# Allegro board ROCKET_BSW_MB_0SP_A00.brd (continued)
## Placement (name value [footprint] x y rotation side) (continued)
PC4708  SC22U6D3V3MX-1-GP  [C603H40]  58.14 62.77 180 top
PC4710  SC330P50V3KX-GP  [C603]  45.5 55.3 90 bottom
PC4801  SC10U25V5KX-GP  [C805H56]  37.5 71.31 0 bottom
PC4802  SC560P50V2KX-2GP  [C402H24]  31.01 83.69 270 top
PC4803  SCD1U16V2KX-3GP  [C402H22]  29.92 73.55 270 top
PC4804  SC470P50V2KX-3GP  [C402H22]  25.96 78.84 0 top
PC4805  SC470P50V2KX-3GP  [C402H22]  29.72 83.14 180 top
PC4806  SCD01U50V2KX-1GP  [C402H22]  34.87 75.05 180 top
PC4807  SC1U10V2KX-1GP  [C402H22]  28.67 74.89 90 top
PC4808  SC2D2U10V3KX-1GP  [C603H36]  33.77 80.68 0 bottom
PC4809  SCD1U16V2KX-3GP  [C402H22]  34.53 73.78 90 top
PC4810  SC100P50V2JN-3GP  [C402H22]  31.01 82.88 270 top
PC4811  SC10U25V5KX-GP  [C805H56]  35.67 71.31 0 bottom
PC4812  SC1KP50V2KX-1GP  [C402H22]  32.71 82.87 90 top
PC4813  SCD22U25V3KX-GP  [C603H40]  34.03 74.82 180 bottom
PC4814  SCD1U16V2KX-3GP  [C402H22]  35.54 79.52 270 top
PC4815  SC1KP50V2KX-1GP  [C402H22]  27.84 73.39 180 top
PC4816  SCD015U25V2KX-GP  [C402H22]  26.77 81.38 180 top
PC4817  SC330P50V3KX-GP  [C603]  45.13 76.27 90 bottom
PC4818  SC100P50V2JN-3GP  [C402H22]  26.34 80.11 270 top
PC4819  SC2200P50V2KX-2GP  [C402H22]  26.22 73.38 0 top
PC4820  SC22U6D3V3MX-1-GP  [C603H40]  55.88 72.61 180 top
PC4821  SC22U6D3V3MX-1-GP  [C603H40]  57.15 72.61 180 top
PC4822  SC22U6D3V3MX-1-GP  [C603H40]  54.61 72.61 180 top
PC4823  SCD1U16V2KX-3GP  [C402H22]  34.1 67.26 90 bottom
PC4834  SCD1U16V2KX-3GP  [C402H22]  28.93 71.92 90 top
PC4839  SCD1U16V2KX-3GP  [C402H22]  27.2 71.92 270 top
PC5000  SC1U10V2KX-1GP  [C402H22]  37.02 47.64 180 bottom
PC5001  SCD1U16V2KX-3GP  [C402H22]  90.14 88.05 0 top
PC5002  SC330P50V2KX-3GP  [C402H22]  92.42 87.92 270 top
PC5003  SCD1U16V2KX-3GP  [C402H22]  83.35 82.82 90 bottom
PC5004  SC4D7U25V5KX-GP  [C805H54]  84.99 90.25 270 bottom
PC5005  SC22U6D3V5MX-2GP  [C805H58]  82.9 79.66 90 bottom
PC5007  SC1U10V2KX-1GP  [C402H22]  93.03 84.29 90 top
PC5008  SC4D7U25V5KX-GP  [C805H54]  84.99 92.05 270 bottom
PC5009  SC2D2U10V3KX-1GP  [C603H36]  91.55 82.66 180 bottom
PC5010  SC22U6D3V5MX-2GP  [C805H58]  82.9 81.46 90 bottom
PC5011  SC22U6D3V5MX-2GP  [C805H58]  81.76 74.25 90 bottom
PC5012  SC22U6D3V5MX-2GP  [C805H58]  81.76 77.85 90 bottom
PC5013  SC22U6D3V5MX-2GP  [C805H58]  81.76 76.05 90 bottom
PC5014  SC10U6D3V3MX-GP  [C603H38]  32.08 50.51 0 bottom
PC5015  SC1U10V2KX-1GP  [C402H22]  33.12 50.49 0 bottom
PC5016  SC10U6D3V3MX-GP  [C603H38]  30.81 50.51 0 bottom
PC5017  SC22P50V2JN-4GP  [C402H22]  34.56 47.64 0 bottom
PC5018  SC22U6D3V3MX-1-GP  [C603H40]  42.53 50.68 0 bottom
PC5019  SC22U6D3V3MX-1-GP  [C603H40]  43.82 50.68 0 bottom
PC5101  SC22U6D3V5MX-2GP  [C805H58]  89.95 27.44 0 bottom
PC5102  SCD1U16V2KX-3GP  [C402H22]  89.54 22.41 180 bottom
PC5103  SC22U6D3V5MX-2GP  [C805H58]  92.66 22.41 180 bottom
PC5104  SC22U6D3V5MX-2GP  [C805H58]  91.76 27.44 0 bottom
PC5105  SC22U6D3V5MX-2GP  [C805H58]  90.86 22.41 180 bottom
PC5106  SC10U25V5KX-GP  [C805H56]  74.75 20.57 90 bottom
PC5107  SCD01U50V2KX-1GP  [C402H22]  74.64 23.68 90 bottom
PC5108  SC10U25V5KX-GP  [C805H56]  74.75 22.37 90 bottom
PC5110  SC1U10V2KX-1GP  [C402H22]  78.28 29.16 0 bottom
PC5111  SC1U10V2KX-1GP  [C402H22]  97.65 23.84 0 bottom
PC5112  SC330P50V2KX-3GP  [C402H22]  75.12 28.23 270 top
PC5113  SC2D2U10V3KX-1GP  [C603H36]  80.24 29.6 0 bottom
PC5114  SC22U6D3V5MX-2GP  [C805H58]  105.82 20.32 180 bottom
PC5115  SC10U6D3V3MX-GP  [C603H38]  102.54 25.71 90 bottom
PC5116  SCD1U16V2KX-3GP  [C402H22]  98.92 19.94 270 top
PC5117  SCD1U25V2KX-GP  [C402H22]  84.38 23.4 90 top
PC5118  SCD1U16V2KX-3GP  [C402H22]  102.59 24.64 90 bottom
PC5119  SCD1U16V2KX-3GP  [C402H22]  95.86 22.16 90 bottom
PC5120  SCD1U16V2KX-3GP  [C402H22]  97.36 21.01 180 bottom
PC5138  SCD1U16V2KX-3GP  [C402H22]  75.12 25.85 180 bottom
PC5219  SC10U6D3V3MX-GP  [C603H38]  30.7 44.6 0 bottom
PC5220  SC10U6D3V3MX-GP  [C603H38]  31.97 44.6 0 bottom
PC5221  SC1U10V2KX-1GP  [C402H22]  33.04 44.6 0 bottom
PC5222  SC22P50V2JN-4GP  [C402H22]  34.7 39.77 90 bottom
PC5223  SC22U6D3V3MX-1-GP  [C603H40]  43.04 42.18 270 bottom
PC5224  SC22U6D3V3MX-1-GP  [C603H40]  43.04 43.45 270 bottom
PC5225  SC1U10V2KX-1GP  [C402H22]  36.73 41.38 180 bottom
PC5301  SC1U10V2KX-1GP  [C402H22]  118.98 100.56 270 top
PC5306  SC1U10V2KX-1GP  [C402H22]  116.88 100.2 90 top
PC5326  SCD1U16V2KX-3GP  [C402H22]  120.88 99.39 0 bottom
PC5401  SC1U10V2KX-1GP  [C402H22]  49 36.94 270 bottom
PC5402  SC10U6D3V3MX-GP  [C603H38]  51.89 40.93 270 bottom
PC5404  SC10U25V5KX-GP  [C805H56]  47.02 47.22 0 bottom
PC5405  SC33P50V2JN-3GP  [C402H22]  45.28 46.59 90 bottom
PC5407  SC10U25V5KX-GP  [C805H56]  48.82 47.22 0 bottom
PC5427  SCD1U16V2KX-3GP  [C402H22]  43.22 39.01 0 bottom
PD4301  P6SMB27A-GP  [DO214AAAKH97]  21.79 71.61 270 bottom
PD4302  SMF18AT1G-GP  [SOD123FLAKH40]  113.28 20.25 270 bottom
PD4303  LBAV99LT1G-1-GP  [SOT23-2D4-312H44]  23.73 63.35 270 bottom
PD4401  SD103AWS-2-GP  [SOD323AKH38]  136.17 15.78 180 top
PD4404  1N4148WS-7-F-GP  [SOD323AKH42]  135.25 36.42 0 bottom
PG4402  GAP-CLOSE-PWR-3-GP  [GAP-CLOSE-PWR-3]  145.71 21.92 0 bottom
PG4403  GAP-CLOSE-PWR-3-GP  [GAP-CLOSE-PWR-3]  145.73 23.65 0 bottom
PG4404  GAP-CLOSE-PWR-3-GP  [GAP-CLOSE-PWR-3]  123.49 24.84 270 bottom
PG4405  GAP-CLOSE-PWR-3-GP  [GAP-CLOSE-PWR-3]  121.77 24.84 270 bottom
PG4407  GAP-CLOSE-PWR-3-GP  [GAP-CLOSE-PWR-3]  132.89 8.59 270 top
PG4408  GAP-CLOSE-PWR-3-GP  [GAP-CLOSE-PWR-3]  131.98 8.59 270 top
PG4409  GAP-CLOSE-PWR-3-GP  [GAP-CLOSE-PWR-3]  123.49 20.32 90 bottom
PG4410  GAP-CLOSE-PWR-3-GP  [GAP-CLOSE-PWR-3]  121.76 20.33 90 bottom
PG4411  GAP-CLOSE-PWR-3-GP  [GAP-CLOSE-PWR-3]  133.77 13.11 90 bottom
PG4517  GAP-CLOSE-PWR-3-GP  [GAP-CLOSE-PWR-3]  23.55 29.67 180 bottom
PG4519  GAP-CLOSE-PWR-3-GP  [GAP-CLOSE-PWR-3]  21.17 19.71 0 bottom
PG4521  GAP-CLOSE-PWR-3-GP  [GAP-CLOSE-PWR-3]  23.63 17.26 270 bottom
PG4523  GAP-CLOSE-PWR-3-GP  [GAP-CLOSE-PWR-3]  21.17 20.47 0 bottom
PG4525  GAP-CLOSE-PWR-3-GP  [GAP-CLOSE-PWR-3]  42.36 16.27 90 bottom
PG4527  GAP-CLOSE-PWR-3-GP  [GAP-CLOSE-PWR-3]  23.55 31.95 180 bottom
PG4528  GAP-CLOSE-PWR-3-GP  [GAP-CLOSE-PWR-3]  23.55 28.91 180 bottom
PG4529  GAP-CLOSE-PWR-3-GP  [GAP-CLOSE-PWR-3]  23.55 28.14 180 bottom
PG4532  GAP-CLOSE-PWR-3-GP  [GAP-CLOSE-PWR-3]  21.17 24.28 0 bottom
PG4533  GAP-CLOSE-PWR-3-GP  [GAP-CLOSE-PWR-3]  21.17 21.99 0 bottom
PG4534  GAP-CLOSE-PWR-3-GP  [GAP-CLOSE-PWR-3]  45.57 19.8 180 top
PG4535  GAP-CLOSE-PWR-3-GP  [GAP-CLOSE-PWR-3]  24.18 26.95 270 bottom
PG4537  GAP-CLOSE-PWR-3-GP  [GAP-CLOSE-PWR-3]  21.17 21.23 0 bottom
PG4538  GAP-CLOSE-PWR-3-GP  [GAP-CLOSE-PWR-3]  21.17 17.42 0 bottom
PG4539  GAP-CLOSE-PWR-3-GP  [GAP-CLOSE-PWR-3]  23.55 30.43 180 bottom
PG4540  GAP-CLOSE-PWR-3-GP  [GAP-CLOSE-PWR-3]  21.17 18.18 0 bottom
PG4541  GAP-CLOSE-PWR-3-GP  [GAP-CLOSE-PWR-3]  21.17 18.94 0 bottom
PG4542  GAP-CLOSE-PWR-3-GP  [GAP-CLOSE-PWR-3]  37.45 27.22 90 top
PG4544  GAP-CLOSE-PWR-3-GP  [GAP-CLOSE-PWR-3]  21.17 23.52 0 bottom
PG4545  GAP-CLOSE-PWR-3-GP  [GAP-CLOSE-PWR-3]  21.17 22.75 0 bottom
PG4546  GAP-CLOSE-PWR-3-GP  [GAP-CLOSE-PWR-3]  23.55 31.19 180 bottom
PG4707  GAP-CLOSE-PWR-3-GP  [GAP-CLOSE-PWR-3]  48.59 61.52 180 bottom
PG4709  GAP-CLOSE-PWR-3-GP  [GAP-CLOSE-PWR-3]  51.92 61.52 0 bottom
PG4801  GAP-CLOSE-PWR-3-GP  [GAP-CLOSE-PWR-3]  51.79 71.5 0 bottom
PG4802  GAP-CLOSE-PWR-3-GP  [GAP-CLOSE-PWR-3]  49.63 71.5 180 bottom
PG5001  GAP-CLOSE-PWR-3-GP  [GAP-CLOSE-PWR-3]  84.23 68.97 90 bottom
PG5002  GAP-CLOSE-PWR-3-GP  [GAP-CLOSE-PWR-3]  44.53 48.26 0 bottom
PG5003  GAP-CLOSE-PWR-3-GP  [GAP-CLOSE-PWR-3]  44.53 49.02 0 bottom
PG5004  GAP-CLOSE-PWR-3-GP  [GAP-CLOSE-PWR-3]  30.78 48.57 90 bottom
PG5005  GAP-CLOSE-PWR-3-GP  [GAP-CLOSE-PWR-3]  31.54 48.57 90 bottom
PG5101  GAP-CLOSE-PWR-3-GP  [GAP-CLOSE-PWR-3]  79.22 20.61 180 bottom
PG5102  GAP-CLOSE-PWR-3-GP  [GAP-CLOSE-PWR-3]  93.83 25.07 0 bottom
PG5103  GAP-CLOSE-PWR-3-GP  [GAP-CLOSE-PWR-3]  79.22 21.38 180 bottom
PG5104  GAP-CLOSE-PWR-3-GP  [GAP-CLOSE-PWR-3]  93.83 26.6 0 bottom
PG5105  GAP-CLOSE-PWR-3-GP  [GAP-CLOSE-PWR-3]  93.83 25.83 0 bottom
PG5106  GAP-CLOSE-PWR-3-GP  [GAP-CLOSE-PWR-3]  79.22 22.14 180 bottom
PG5107  GAP-CLOSE-PWR-3-GP  [GAP-CLOSE-PWR-3]  79.22 19.85 180 bottom
PG5108  GAP-CLOSE-PWR-3-GP  [GAP-CLOSE-PWR-3]  93.83 24.31 0 bottom
PG5109  GAP-CLOSE-PWR-3-GP  [GAP-CLOSE-PWR-3]  93.83 27.36 0 bottom
PG5117  GAP-CLOSE-PWR-3-GP  [GAP-CLOSE-PWR-3]  105.92 22.72 90 bottom
PG5118  GAP-CLOSE-PWR-3-GP  [GAP-CLOSE-PWR-3]  106.68 22.72 90 bottom
PG5207  GAP-CLOSE-PWR-3-GP  [GAP-CLOSE-PWR-3]  31.79 42.61 90 bottom
PG5208  GAP-CLOSE-PWR-3-GP  [GAP-CLOSE-PWR-3]  31.02 42.61 90 bottom
PG5209  GAP-CLOSE-PWR-3-GP  [GAP-CLOSE-PWR-3]  42.67 44.97 0 bottom
PG5210  GAP-CLOSE-PWR-3-GP  [GAP-CLOSE-PWR-3]  42.67 45.73 0 bottom
PG5408  GAP-CLOSE-PWR-3-GP  [GAP-CLOSE-PWR-3]  50.44 45.73 0 bottom
PG5409  GAP-CLOSE-PWR-3-GP  [GAP-CLOSE-PWR-3]  50.44 46.65 0 bottom
PL4401  IND-2D2UH-179-GP  [L7066-1830-UH119]  129.28 21.58 90 bottom
PL4501  COIL-1D5UH-43-GP  [L4947-1015H119]  33.14 29.3 90 bottom
PL4502  COIL-1D5UH-43-GP  [L4947-1015H119]  34.13 21.22 90 bottom
PL4701  IND-D36UH-26-GP-U  [L6965-1330-UH119]  50.21 61.52 270 bottom
PL4801  IND-D22UH-37-GP  [L7066-1830-UH119]  50.67 71.5 270 bottom
PL5001  COIL-1UH-73-GP  [L4947-1115H119]  87.68 80.09 180 bottom
PL5002  IND-2D2UH-296-GP  [L3030-3009H60]  39.67 49.94 270 bottom
PL5101  COIL-1UH-73-GP  [L4947-1115H119]  84.93 24.86 270 bottom
PL5201  IND-2D2UH-296-GP  [L3030-3009H60]  39.59 44.42 270 bottom
PQ4301  DMN5L06K-7-GP  [SOT23DGS2D4H48]  27.58 64.36 180 bottom
PQ4302  LMBT3904LT1G-GP  [SOT23CBE2D4H44]  31.36 66.89 270 bottom
PQ4304  LTC024EUB-FS8-GP  [SC70-2D2-312H44]  19.36 67.3 180 bottom
PQ4305  LTA024EUB-FS8-GP  [SC70-2D2-312H44]  22.38 67.3 0 bottom
PQ4309  2N7002K-2-GP  [SOT23DGS2D4H44]  30.02 70.69 180 bottom
PQ4402  2N7002KDW-GP  [SOT-363H44]  148.97 26.31 270 bottom
PQ4407  2N7002KDW-GP  [SOT-363H44]  135.7 9.65 180 bottom
PQ4408  2N7002KDW-GP  [SOT-363H44]  149.11 21.53 270 bottom
PQ4409  LMBT3906LT1G-1-GP  [SOT23CBE2D4H44]  138.07 35.17 0 bottom
PQ4410  2N7002KDW-GP  [SOT-363H44]  135.56 30.84 270 bottom
PQ4414  2N7002K-2-GP  [SOT23DGS2D4H44]  142.81 32.24 270 bottom
PR4168  4K02R2F-GP  [R402H16]  25.51 52.52 180 bottom
PR4302  15KR2F-GP  [R402H16]  27.9 68.18 180 top
PR4303  10KR2J-3-GP  [R402H16]  29.85 64.85 0 top
PR4306  2K2R2J-2-GP  [R402H16]  20.88 62.87 180 top
PR4307  33R2J-2-GP  [R402H16]  17.68 63.73 180 bottom
PR4309  240KR3-GP  [R603H22]  26.33 67.92 180 bottom
PR4310  47KR3J-L-GP  [R603H22]  27.6 67.92 0 bottom
PR4311  100KR2J-1-GP  [R402H16]  27.48 66.92 90 top
PR4312  1KR2J-1-GP  [R402H16]  28.53 66.02 270 top
PR4316  3K3R6J-GP  [R1206H28]  28.99 73.63 270 bottom
PR4401  10KR2F-2-GP  [R402H16]  144.86 21.78 0 top
PR4402  D01R3721F-GP-U  [R3720H40]  143.51 22.78 0 bottom
PR4403  100KR2J-1-GP  [R402H16]  143.73 20.46 270 bottom
PR4404  3KR5J-GP  [R805H24]  146.25 14.68 0 bottom
PR4405  470KR2J-2-GP  [R402H16]  119.34 23.7 0 top
PR4406  0R2J-2-GP  [R402H16]  126.8 14.58 0 top
PR4407  287KR2F-GP  [R402H16]  127.22 10.31 90 top
PR4408  10R5J-GP  [R805H24]  130.32 17.49 0 top
PR4409  -  [0R0603-PAD]  133.32 16.46 0 bottom
PR4410  6D8R2F-GP  [R402H16]  142.39 29.1 0 bottom
PR4411  102KR2F-GP  [R402H16]  127.27 11.41 90 top
PR4412  3K3R2F-2-GP  [R402H16]  132.03 7.3 0 bottom
PR4413  169KR2F-L-GP  [R402H16]  130.45 12.2 270 bottom
PR4414  3D3MR2J-GP  [R402H16]  128.24 12.68 0 top
PR4415  3K3R2F-2-GP  [R402H16]  131.18 7.3 0 bottom
PR4416  D01R3721F-GP-U  [R3720H40]  122.64 22.62 90 bottom
PR4417  100KR2J-1-GP  [R402H16]  134.55 8.86 270 top
PR4418  0R2J-2-GP  [R402H16]  136.04 11.31 270 top
PR4419  100KR2J-1-GP  [R402H16]  149.48 19.15 0 bottom
PR4420  7D5R2F-GP  [R402H16]  136.22 12.39 90 top
PR4421  10R2F-L-GP  [R402H14]  136.08 13.3 90 top
PR4422  -  [0R0402-PAD]  126.02 9.37 270 top
PR4423  59KR2F-GP  [R402H16]  133.57 10.7 0 bottom
PR4424  8K45R2F-2-GP  [R402H16]  132.68 10.32 0 bottom
PR4425  100KR2J-1-GP  [R402H16]  126.91 12.62 270 bottom
PR4426  -  [0R0402-PAD]  149.28 23.61 270 bottom
PR4427  78K7R2F-GP  [R402H16]  135.76 6.91 180 bottom
PR4428  100KR2J-1-GP  [R402H16]  148.1 18.74 270 bottom
PR4429  309KR2F-GP  [R402H16]  134.92 6.91 0 bottom
PR4430  100KR2J-1-GP  [R402H16]  127.12 12.87 0 top
PR4431  47KR2F-GP  [R402H16]  130.45 11.38 270 bottom
PR4432  120KR2F-L-GP  [R402H16]  125.24 13.27 270 top
PR4433  120KR2F-L-GP  [R402H16]  124.93 10.74 270 top
PR4434  100KR2J-1-GP  [R402H16]  124.93 11.57 90 top
PR4435  10KR2F-2-GP  [R402H16]  136.06 10.47 90 top
PR4436  120KR2F-L-GP  [R402H16]  148.1 19.57 90 bottom
PR4437  160KR2F-GP  [R402H16]  149.25 14.36 90 top
PR4438  100KR2J-1-GP  [R402H16]  125.23 12.43 270 top
PR4446  20KR2F-L-GP  [R402H16]  145.81 30.08 90 bottom
PR4448  0R2J-2-GP  [R402H16]  140.29 28.69 270 bottom
PR4454  10R2F-L-GP  [R402H14]  140.3 29.52 270 bottom
PR4464  680KR2J-GP  [R402H16]  139.33 32.44 180 bottom
PR4465  0R2J-2-GP  [R402H16]  141.57 34.44 90 bottom
PR4466  0R2J-2-GP  [R402H16]  139.05 30.35 270 bottom
PR4467  1MR2J-1-GP  [R402H16]  137.94 37.48 90 bottom
PR4468  0R2J-2-GP  [R402H16]  140.13 38.55 90 bottom
PR4469  100KR2J-1-GP  [R402H16]  140.29 36.21 0 bottom
PR4470  100KR2F-L1-GP  [R402H16]  132.9 29.6 90 bottom
PR4472  100KR2F-L1-GP  [R402H16]  146.81 34.53 270 bottom
PR4473  10KR2F-2-GP  [R402H16]  134.83 32.79 270 bottom
PR4474  100KR2J-1-GP  [R402H16]  143.28 34.44 90 bottom
PR4475  0R2J-2-GP  [R402H16]  138.5 32.44 180 bottom
PR4476  0R2J-2-GP  [R402H16]  139 31.17 90 bottom
PR4501  -  [0R0603-PAD]  38.24 33.27 270 top
PR4502  -  [0R0603-PAD]  39.93 23.62 270 top
PR4504  -  [0R0402-PAD]  47.38 29.3 0 bottom
PR4506  1KR2F-3-GP  [R402H16]  39.95 26.79 180 bottom
PR4507  1KR2F-3-GP  [R402H16]  41.44 16.4 0 top
PR4510  -  [0R0402-PAD]  48.22 21.43 180 top
PR4511  -  [0R0402-PAD]  48.29 18.35 90 top
PR4512  1KR2F-3-GP  [R402H16]  46.51 19.27 270 bottom
PR4513  200KR2F-L1-GP  [R402H16]  48.2 19.27 270 bottom
PR4514  -  [0R0402-PAD]  47.79 19.16 270 top
PR4515  1KR2F-3-GP  [R402H16]  46.56 28.13 180 bottom
PR4516  1MR2J-1-GP  [R402H16]  47.85 17 0 top
PR4517  200KR2F-L1-GP  [R402H16]  44.78 28.13 0 bottom
PR4518  1MR2J-1-GP  [R402H16]  41.92 28.59 90 top
PR4532  -  [0R0603-PAD]  38.06 25.85 90 top
PR4534  100KR2J-1-GP  [R402H16]  45.67 29.82 180 bottom
PR4601  200R2F-L-GP  [R402H16]  32.45 63.54 270 top
PR4602  200R2F-L-GP  [R402H16]  32.69 67.03 90 top
PR4603  47R2F-GP  [R402H16]  23.36 56.12 90 top
PR4604  1KR2F-3-GP  [R402H16]  24.44 57.01 0 bottom
PR4605  -  [0R0402-PAD]  22.27 60.25 270 top
PR4606  75KR2F-GP  [R402H16]  25.17 50.83 0 bottom
PR4607  1KR2J-1-GP  [R402H16]  33.55 60.89 180 bottom
PR4609  560KR2F-GP  [R402H16]  21.62 52.46 270 top
PR4610  1K5R2F-2-GP  [R402H16]  22.27 58.62 270 top
PR4612  2D2R3-1-U-GP  [R603H22]  33.17 59.42 270 bottom
PR4613  10R2J-2-GP  [R402H14]  28.55 51.53 90 bottom
PR4614  100KR2F-L1-GP  [R402H16]  25.99 50.83 0 bottom
PR4615  14K7R2F-L-GP  [R402H16]  24.48 53.61 180 bottom
PR4616  1K3R2F-1-GP  [R402H16]  22.99 53.62 270 top
PR4617  215KR3F-1-GP  [R603H22]  27.04 50.82 180 bottom
PR4619  46K4R2F-2-GP  [R402H16]  21.72 51.19 0 top
PR4620  2D2R3J-2-GP  [R603H22]  23.44 59.67 270 bottom
PR4621  56D2R2F  [R402H16]  27.04 61.64 180 bottom
PR4635  20KR2J-L2-GP  [R402H16]  26.2 61.38 180 bottom
PR4637  1R3J-L1-GP  [R603H22]  33.68 53.26 90 bottom
PR4638  10KR2J-3-GP  [R402H16]  22.52 61.09 270 top
PR4640  -  [0R0402-PAD]  27.88 61.62 0 bottom
PR4643  10KR2F-2-GP  [R402H16]  34.07 55.65 0 bottom
PR4644  -  [0R0402-PAD]  32.23 54.32 270 bottom
PR4645  200R2J-L1-GP  [R402H16]  32.04 62.64 180 bottom
PR4648  NTC-100K-20-GP  [NTC-402H24-U]  49.5 57.19 270 bottom
PR4649  10KR2J-3-GP  [R402H16]  33.63 61.32 0 top
PR4652  -  [0R0402-PAD]  58.82 43.59 315 top
PR4658  -  [0R0402-PAD]  59.42 43 315 top
PR4660  -  [0R0402-PAD]  32.8 55.16 270 bottom
PR4661  NTC-100K-20-GP  [NTC-402H24-U]  45.41 56.5 90 bottom
PR4663  49D9R2F-GP  [R402H16]  29.56 61.62 0 bottom
PR4665  300R2F-GP  [R402H16]  31.55 67.87 270 top
PR4669  20R2J-3-GP  [R402H16]  28.72 61.62 0 bottom
PR4676  100R2F-L1-GP-U  [R402H14]  62.72 43.72 270 top
PR4678  100R2F-L1-GP-U  [R402H14]  62.72 44.55 270 top
PR4684  31K6R2F-GP  [R402H16]  29.19 53.24 270 bottom
PR4704  2D2R5F-2-GP  [R805H24]  47.59 56.32 180 bottom
PR4801  47R2F-GP  [R402H16]  26.34 77.59 90 top
PR4802  560KR2F-GP  [R402H16]  28.77 78.82 270 bottom
PR4803  1KR2F-3-GP  [R402H16]  26.77 78.84 0 top
PR4804  200R2F-L-GP  [R402H16]  34.35 69.53 180 bottom
PR4805  200R2F-L-GP  [R402H16]  33.52 69.53 180 bottom
PR4807  -  [0R0402-PAD]  30.82 69.15 0 top
PR4808  -  [0R0402-PAD]  27.53 70.67 180 top
PR4809  -  [0R0402-PAD]  28.39 70.66 180 top
PR4810  NTC-100K-20-GP  [NTC-402H24-U]  50.32 67.13 270 bottom
PR4812  NTC-100K-20-GP  [NTC-402H24-U]  40.41 76.51 270 bottom
PR4813  10KR2J-3-GP  [R402H16]  29.92 72.74 270 top
PR4814  20KR2J-L2-GP  [R402H16]  31.14 70.4 270 top
PR4816  56D2R2F  [R402H16]  30.93 71.93 270 top
PR4817  2D2R3J-2-GP  [R603H22]  29.71 75.35 90 bottom
PR4818  1R3J-L1-GP  [R603H22]  32.87 78.3 0 bottom
PR4819  34KR2F-GP  [R402H16]  28.88 83.14 180 top
PR4820  3K6R2F-GP  [R402H16]  28.07 83.14 180 top
PR4821  41K2R2F-GP  [R402H16]  34.12 82.24 180 top
PR4822  48D7KR2F-GP  [R402H16]  35.54 80.37 90 top
PR4823  2D2R3-1-U-GP  [R603H22]  32.76 74.82 180 bottom
PR4824  10R2J-2-GP  [R402H14]  32.72 83.69 270 top
PR4825  75KR2F-GP  [R402H16]  30.58 84.95 0 top
PR4827  1KR2J-1-GP  [R402H16]  35.71 75.05 180 top
PR4828  14K7R2F-L-GP  [R402H16]  27.23 83.14 180 top
PR4830  100KR2F-L1-GP  [R402H16]  31.42 84.95 0 top
PR4831  1K3R2F-1-GP  [R402H16]  25.93 81.39 0 top
PR4832  200KR3F-GP  [R603H22]  33.06 84.75 90 top
PR4833  10KR2F-2-GP  [R402H16]  36.83 79.11 180 top
PR4834  -  [0R0402-PAD]  35.54 78.71 90 top
PR4835  1K5R2F-2-GP  [R402H16]  27.03 73.39 0 top
PR4836  -  [0R0402-PAD]  28.66 73.39 0 top
PR4843  300R2F-GP  [R402H16]  32.68 69.53 180 bottom
PR4847  2D2R5F-2-GP  [R805H24]  47.77 76.27 90 bottom
PR4854  49D9R2F-GP  [R402H16]  33.3 71.78 0 top
PR4855  20R2J-3-GP  [R402H16]  32.43 71.78 0 top
PR4875  200R2J-L1-GP  [R402H16]  34.13 71.78 0 top
PR5001  -  [0R0603-PAD]  86.92 86.58 0 top
PR5002  470KR2F-GP  [R402H16]  92.3 87 270 bottom
PR5003  1MR2J-1-GP  [R402H16]  89.31 88.05 0 top
PR5004  -  [0R0402-PAD]  90.4 90.96 0 top
PR5005  100KR2F-L1-GP  [R402H16]  92.89 85.14 90 top
PR5006  100R2F-L1-GP-U  [R402H14]  93.7 87.5 0 top
PR5007  -  [0R0402-PAD]  91.34 84.28 270 top
PR5008  1KR2J-1-GP  [R402H16]  92.3 87.82 90 bottom
PR5009  -  [0R0402-PAD]  35.37 47.66 180 top
PR5010  53K6R2F-GP  [R402H16]  35.38 47.64 180 bottom
PR5011  49K9R2F-L-GP  [R402H16]  33.75 47.64 0 bottom
PR5012  10KR2J-3-GP  [R402H16]  32.96 47.51 90 top
PR5013  100KR2J-1-GP  [R402H16]  88.97 91.21 0 top
PR5014  75KR2F-GP  [R402H16]  92.42 87.11 270 top
PR5039  10R2F-L-GP  [R402H14]  93.42 85.98 90 top
PR5066  -  [0R0402-PAD]  88.51 89.94 90 top
PR5101  -  [0R0603-PAD]  82.21 23.52 90 top
PR5102  -  [0R0402-PAD]  79.1 29.16 0 bottom
PR5103  42K2R2F-L-GP  [R402H16]  75.12 29.05 270 top
PR5104  33K2R2F-GP  [R402H16]  73.75 28.62 180 top
PR5105  -  [0R0402-PAD]  74.18 27.38 90 top
PR5106  0R2J-2-GP  [R402H16]  73.79 29.1 180 bottom
PR5107  -  [0R0402-PAD]  75.11 25.6 90 top
PR5114  -  [0R0402-PAD]  95.84 22 90 top
PR5117  -  [0R0402-PAD]  97.34 21.71 0 top
PR5125  -  [0R0402-PAD]  95.53 20.59 90 top
PR5201  -  [0R0402-PAD]  37.6 41.38 0 bottom
PR5202  20KR2J-L2-GP  [R402H16]  38.45 41.37 0 bottom
PR5211  100KR2F-L1-GP  [R402H16]  34.7 41.17 270 bottom
PR5213  49K9R2F-L-GP  [R402H16]  34.7 42.01 90 bottom
PR5218  10KR2J-3-GP  [R402H16]  32.81 41.37 270 bottom
PR5315  0R2J-2-GP  [R402H16]  121.7 99.39 180 bottom
PR5401  47KR2J-2-GP  [R402H16]  44.04 39.01 0 bottom
PR5417  -  [0R0402-PAD]  42.39 39.02 180 bottom
PR5419  7K32R2F-GP  [R402H16]  45.28 45.77 90 bottom
PR5420  13K3R2F-L1-GP  [R402H16]  45.28 47.4 270 bottom
PT4701  ST330U2D5VBM-4-GP  [CT3528H79]  56.49 64.26 0 bottom
PT4702  SE33U25VM-11-GP  [CT7343H83]  39.62 55.69 270 bottom
PT4801  ST330U2D5VBM-4-GP  [CT3528H79]  57.09 73.82 0 bottom
PU4301  SI7121DN-T1-GE3-GP  [PPAK-8P-2H45]  143.13 12.51 90 bottom
PU4402  SI7121DN-T1-GE3-GP  [PPAK-8P-2H45]  143.12 16.62 0 bottom
PU4403  SI7121DN-T1-GE3-GP  [PPAK-8P-2H45]  118.5 21.54 0 bottom
PU4404  BQ24727RGRR-1-GP  [QFN20G3D5-G2D15H40]  132.27 12.13 90 top
PU4405  HS8K11TB-GP  [DFN8F3-G2PH26]  135.87 21.55 180 bottom
PU4407  INA199A1-GP  [SC70-6H44]  144.34 27.88 180 bottom
PU4502  SY8286BRAC-GP  [QFN20Z3-G1D1H36]  40.43 30.38 180 bottom
PU4503  SY8286CRAC-GP  [QFN20Z3-G1D1H36]  41.74 20.47 180 bottom
PU4601  NCP81201MNTXG-GP-U2  [LFQFN28J4-G2D7-UH40]  28.37 57.25 180 bottom
PU4701  FDMS3600-02-RJK0215-COLAY-GP  [PPAK-8P-G5324H44-COLAY]  42.42 62.31 0 bottom
PU4801  FDMS3600-02-RJK0215-COLAY-GP  [PPAK-8P-G5324H44-COLAY]  42.85 71.27 180 bottom
PU4802  NCP81201MNTXG-GP-U2  [LFQFN28J4-G2D7-UH40]  30.89 77.95 180 top
PU5001  SY8286RAC-GP  [QFN20Z3-G1D1H36]  88.57 86.49 270 bottom
PU5002  SYW232DFC-GP  [DFN8G2-G1711H26]  35.43 50.06 270 bottom
PU5101  SY8286RAC-GP  [QFN20Z3-G1D1H36]  78.78 25.12 0 bottom
PU5102  APL5338XAI-TRG-GP  [MSOP10-G2D5H44]  101.57 22.18 270 bottom
PU5204  SYW232DFC-GP  [DFN8G2-G1711H26]  35.39 43.97 270 bottom
PU5301  S-1339D15-M5001-GP  [SOT-23-5H52]  116.87 99.12 270 bottom
PU5402  APL5930KAI-TRG-GP  [SOIC8-G3530H63]  47.45 41.38 0 bottom
Q801  2N7002K-2-GP  [SOT23DGS2D4H44]  50.46 53.2 90 bottom
Q1606  PJT138KA-GP  [SOT-363H44]  56.98 8.17 180 top
Q1622  2N7002KDW-GP  [SOT-363H44]  52.26 7.73 180 top
Q1801  2N7002KDW-GP  [SOT-363H44]  57.61 34.8 90 bottom
Q1810  2N7002KDW-GP  [SOT-363H44]  58.89 40.69 180 bottom
Q1811  DMN5L06K-7-GP  [SOT23DGS2D4H48]  52.29 33.72 90 bottom
Q1812  SSM3K329R-1-GP  [SOT23DGS2D4H35]  62.61 40.62 0 bottom
Q1813  2N7002KDW-GP  [SOT-363H44]  61.16 34.34 0 bottom
Q1814  PJT138KA-GP  [SOT-363H44]  60.14 46.96 225 bottom
Q1901  2N7002K-2-GP  [SOT23DGS2D4H44]  76.47 77.17 90 bottom
Q2401  LMBT3906LT1G-1-GP  [SOT23CBE2D4H44]  53.82 3.95 90 bottom
Q2402  2N7002K-2-GP  [SOT23DGS2D4H44]  69.99 28.54 90 bottom
Q2403  2N7002K-2-GP  [SOT23DGS2D4H44]  61.21 3.96 180 bottom
Q2404  DMP2130L-7-GP  [SOT23DGS2D4H48]  57.63 3.96 180 bottom
Q2501  BAS40C-2-GP  [SOT-23-9H44]  134.72 98.95 0 bottom
Q2502  2N7002K-2-GP  [SOT23DGS2D4H44]  130.99 98.96 0 bottom
Q2601  LMBT3904LT1G-GP  [SOT23CBE2D4H44]  82.78 29.57 90 bottom
Q2603  2N7002K-2-GP  [SOT23DGS2D4H44]  71.93 77.07 180 bottom
Q2604  2N7002KDW-GP  [SOT-363H44]  95.94 81.45 0 bottom
Q2901  2N7002K-2-GP  [SOT23DGS2D4H44]  148.5 95.17 0 bottom
Q3301  2N7002K-2-GP  [SOT23DGS2D4H44]  6.91 41.94 270 bottom
Q4001  2N7002KDW-GP  [SOT-363H44]  143.18 37.06 0 bottom
Q4014  2N7002KDW-GP  [SOT-363H44]  142.78 41.66 0 bottom
Q4015  2N7002K-2-GP  [SOT23DGS2D4H44]  136.88 40.77 90 bottom
Q4016  2N7002KDW-GP  [SOT-363H44]  136.81 52.11 180 bottom
Q4017  2N7002K-2-GP  [SOT23DGS2D4H44]  135.88 45.91 270 bottom
Q4020  2N7002K-2-GP  [SOT23DGS2D4H44]  149.12 31.25 180 bottom
Q5501  LMBT3904LT1G-GP  [SOT23CBE2D4H44]  58.65 79.2 0 bottom
Q5503  LMBT3904LT1G-GP  [SOT23CBE2D4H44]  54.22 79.22 180 bottom
Q5506  2N7002K-2-GP  [SOT23DGS2D4H44]  46.56 79.17 180 bottom
Q5701  2N7002KDW-GP  [SOT-363H44]  14.68 65.61 270 bottom
Q5703  DMN5L06K-7-GP  [SOT23DGS2D4H48]  15.98 69.8 180 bottom
Q5705  DMN5L06K-7-GP  [SOT23DGS2D4H48]  15.92 73.46 270 bottom
Q5707  2N7002K-2-GP  [SOT23DGS2D4H44]  19.92 63.42 0 bottom
Q6301  DMN5L06K-7-GP  [SOT23DGS2D4H48]  127.43 99.08 180 bottom
Q6403  DDTA144VCA-7-F-GP  [SOT23CBE2D4H44]  12.05 14.88 0 bottom
Q6404  DDTA144VCA-7-F-GP  [SOT23CBE2D4H44]  8.17 14.88 0 bottom
Q6501  DRA2144V0L-GP  [SOT23CBE2D8H56]  73.59 15.44 180 bottom
Q6502  2N7002K-2-GP  [SOT23DGS2D4H44]  47.8 7.63 270 bottom
Q6503  DMP2130L-7-GP  [SOT23DGS2D4H48]  44.32 3.93 90 bottom
Q6504  DMP2130L-7-GP  [SOT23DGS2D4H48]  48.17 3.94 90 bottom
Q6507  2N7002KDW-GP  [SOT-363H44]  46.48 5.84 0 top
R504  182R2F-GP  [R402H16]  86 60.02 135 top
R508  182R2F-GP  [R402H16]  86.36 62.82 135 top
R801  402R2F-GP  [R402H16]  79.86 38.99 180 top
R802  402R2F-GP  [R402H16]  74.29 43.41 270 top
R803  100KR2J-1-GP  [R402H16]  81.13 39.75 180 top
R804  100KR2J-1-GP  [R402H16]  81.54 38.46 90 top
R806  10KR2J-3-GP  [R402H16]  47.51 52.44 270 top
R807  -  [0R0402-PAD]  64.98 59 135 top
R808  10KR2J-3-GP  [R402H16]  62.2 51.21 270 top
R809  10KR2J-3-GP  [R402H16]  62.33 52.07 90 top
R810  10KR2J-3-GP  [R402H16]  60.18 48.52 225 top
R812  10KR2J-3-GP  [R402H16]  60.77 49.7 135 top
R813  1MR2J-1-GP  [R402H16]  79.89 40.91 135 top
R814  100R2F-L1-GP-U  [R402H14]  67.28 52.41 315 top
R815  80D6R2F-L-GP  [R402H16]  66.35 54.52 225 top
R817  150R2F-1-GP  [R402H16]  71.58 41.03 135 top
R818  10KR2J-3-GP  [R402H16]  54.57 52.12 90 top
R819  10KR2J-3-GP  [R402H16]  56.25 52.21 90 top
R1202  4K7R2F-GP  [R402H16]  124.73 87.05 180 top
R1203  -  [0R0402-PAD]  122.83 87 180 top
R1204  4K7R2F-GP  [R402H16]  121.97 86.99 0 top
R1205  4K7R2F-GP  [R402H16]  128.12 34.03 180 top
R1206  4K7R2F-GP  [R402H16]  129.07 34.03 0 top
R1207  -  [0R0402-PAD]  126.67 34.47 90 top
R1208  240R2F-1-GP  [R402H16]  125.05 45.34 90 top
R1209  240R2F-1-GP  [R402H16]  124.6 62.95 0 top
R1210  240R2F-1-GP  [R402H16]  124.7 34.01 0 top
R1211  240R2F-1-GP  [R402H16]  125.46 76.45 90 top
R1217  80D6R2F-L-GP  [R402H16]  131.63 56.89 180 top
R1218  80D6R2F-L-GP  [R402H16]  131.98 62.27 90 top
R1219  80D6R2F-L-GP  [R402H16]  132.67 58.2 180 top
R1220  80D6R2F-L-GP  [R402H16]  139.7 60.48 0 top
R1221  80D6R2F-L-GP  [R402H16]  130.79 56.9 180 top
R1222  80D6R2F-L-GP  [R402H16]  137.32 58.1 90 top
R1223  80D6R2F-L-GP  [R402H16]  131.96 61.44 90 top
R1224  80D6R2F-L-GP  [R402H16]  137.31 57.25 90 top
R1225  80D6R2F-L-GP  [R402H16]  138.85 60.48 0 top
R1226  80D6R2F-L-GP  [R402H16]  135.05 56.46 180 top
R1227  80D6R2F-L-GP  [R402H16]  122.74 60.11 180 top
R1228  80D6R2F-L-GP  [R402H16]  135.92 57.71 0 top
R1229  80D6R2F-L-GP  [R402H16]  128.99 56.67 0 top
R1230  80D6R2F-L-GP  [R402H16]  138.01 60.48 0 top
R1231  80D6R2F-L-GP  [R402H16]  134.21 58.4 0 top
R1232  80D6R2F-L-GP  [R402H16]  124.18 55.61 0 top
R1233  80D6R2F-L-GP  [R402H16]  120.73 55.02 0 top
R1234  80D6R2F-L-GP  [R402H16]  125.46 62.13 180 top
R1235  80D6R2F-L-GP  [R402H16]  116.49 61.24 180 top
R1236  80D6R2F-L-GP  [R402H16]  115.61 61.25 180 top
R1237  80D6R2F-L-GP  [R402H16]  117.92 62.21 180 top
R1240  80D6R2F-L-GP  [R402H16]  123.57 60.11 180 top
R1241  80D6R2F-L-GP  [R402H16]  128.98 61.19 0 top
R1242  80D6R2F-L-GP  [R402H16]  136.61 60.55 0 top
R1244  80D6R2F-L-GP  [R402H16]  127.56 62.01 180 top
R1245  80D6R2F-L-GP  [R402H16]  129.87 55.88 0 top
R1246  80D6R2F-L-GP  [R402H16]  121.93 62.55 180 top
R1503  10KR2F-2-GP  [R402H16]  86.17 44.87 315 top
R1504  10KR2F-2-GP  [R402H16]  92.81 38.97 225 bottom
R1506  10KR2F-2-GP  [R402H16]  96.32 38.06 45 bottom
R1508  10KR2F-2-GP  [R402H16]  93.73 39.23 225 bottom
R1513  10KR2F-2-GP  [R402H16]  91.54 41.66 45 bottom
R1514  10KR2F-2-GP  [R402H16]  94.48 40.86 135 bottom
R1515  10KR2F-2-GP  [R402H16]  93.87 41.46 315 bottom
R1517  10KR2F-2-GP  [R402H16]  95.71 37.47 45 bottom
R1519  4K7R2F-GP  [R402H16]  95.53 43.53 315 bottom
R1520  10KR2F-2-GP  [R402H16]  94.19 37.73 135 bottom
R1522  4K7R2F-GP  [R402H16]  89.16 39.57 45 bottom
R1523  10KR2F-2-GP  [R402H16]  91.55 37.4 45 bottom
R1524  10KR2F-2-GP  [R402H16]  89.79 40.2 45 bottom
R1525  1KR2J-1-GP  [R402H16]  92.15 37.98 45 bottom
R1526  10KR2F-2-GP  [R402H16]  88.39 38.78 225 bottom
R1527  10KR2F-2-GP  [R402H16]  90.92 36.79 45 bottom
R1529  10KR2F-2-GP  [R402H16]  83.1 41.58 225 top
R1531  100KR2J-1-GP  [R402H16]  94.86 42.3 45 bottom
R1532  100KR2J-1-GP  [R402H16]  87.26 44.13 225 top
R1535  10KR2F-2-GP  [R402H16]  84 42.52 225 top
R1536  100KR2J-1-GP  [R402H16]  70.98 41.62 135 top
R1537  10KR2F-2-GP  [R402H16]  69.21 39.06 315 bottom
R1601  2K49R2F-GP  [R402H16]  70.92 48.49 225 top
R1603  200KR2F-L-GP  [R402H16]  57.02 46.39 0 bottom
R1610  2K2R2J-2-GP  [R402H16]  49.42 7.8 180 top
R1611  0R2J-2-GP  [R402H16]  74.14 34.77 45 bottom
R1615  -  [0R0402-PAD]  96.15 42.91 315 bottom
R1616  2K2R2J-2-GP  [R402H16]  51.28 3.94 90 top
R1617  0R2J-2-GP  [R402H16]  76.62 39.26 270 top
R1618  0R2J-2-GP  [R402H16]  51.31 10.37 180 top
R1619  0R2J-2-GP  [R402H16]  52.54 4.33 180 top
R1620  2K2R2J-2-GP  [R402H16]  50.25 7.81 180 top
R1621  2K2R2J-2-GP  [R402H16]  54.25 6.97 180 top
R1622  2K2R2J-2-GP  [R402H16]  51.28 4.77 90 top
R1623  2K2R2J-2-GP  [R402H16]  52.58 10.53 90 top
R1636  49D9R2F-GP  [R402H16]  70.34 47.91 225 top
R1637  45D3R2F-L-GP  [R402H16]  75.61 44.9 90 top
R1639  100R2F-L1-GP-U  [R402H14]  82.86 47.58 225 top
R1641  113R2F-GP  [R402H16]  75.41 38.4 270 top
R1642  402R2F-GP  [R402H16]  72.89 43.84 315 top
R1802  33R2J-2-GP  [R402H16]  62.68 63.36 90 top
R1803  33R2J-2-GP  [R402H16]  60.57 58.6 0 top
R1807  -  [0R0402-PAD]  60.22 60.31 0 top
R1808  10KR2J-3-GP  [R402H16]  63.19 49.75 225 top
R1809  -  [0R0402-PAD]  72.03 26.36 0 top
R1810  -  [0R0402-PAD]  57.83 25.75 270 top
R1811  0R2J-2-GP  [R402H16]  52.48 35.94 270 bottom
R1813  2K2R2J-2-GP  [R402H16]  63.77 50.33 225 top
R1816  10MR2J-L-GP  [R402H16]  55.65 50.27 0 bottom
R1820  10KR2J-3-GP  [R402H16]  59.18 30.89 90 bottom
R1821  -  [0R0402-PAD]  78.18 27.4 270 top
R1823  10KR2J-3-GP  [R402H16]  67.45 49.17 315 top
R1824  200R2F-L-GP  [R402H16]  32.69 66.2 90 top
R1825  2K7R2J-GP  [R402H16]  71.21 70.15 135 bottom
R1826  100KR2J-1-GP  [R402H16]  58.62 32.36 0 bottom
R1827  -  [0R0402-PAD]  60.01 40.07 180 top
R1828  100KR2J-1-GP  [R402H16]  62.1 31.4 270 bottom
R1830  10KR2J-3-GP  [R402H16]  56.6 38.89 180 bottom
R1833  -  [0R0402-PAD]  78.18 29.05 270 top
R1835  -  [0R0402-PAD]  78.18 28.22 270 top
R1839  20KR2J-L2-GP  [R402H16]  61.35 48.51 45 top
R1841  1KR2J-1-GP  [R402H16]  58.74 37.38 270 bottom
R1842  2K2R2J-2-GP  [R402H16]  60.82 40.07 180 top
R1843  10KR2J-3-GP  [R402H16]  61.04 42.78 270 top
R1844  -  [0R0402-PAD]  56.95 32.36 180 bottom
R1845  0R2J-2-GP  [R402H16]  55.35 35.94 0 bottom
R1848  100R2F-L1-GP-U  [R402H14]  63.98 43.31 180 top
R1849  100R2F-L1-GP-U  [R402H14]  63.98 45 0 top
R1850  10KR2J-3-GP  [R402H16]  51.13 36.76 90 bottom
R1851  100R2F-L1-GP-U  [R402H14]  58.67 41.91 225 top
R1852  100R2F-L1-GP-U  [R402H14]  57.48 43.11 45 top
R1856  10KR2J-3-GP  [R402H16]  57.32 40.07 0 top
R1858  10KR2J-3-GP  [R402H16]  54.61 32.13 180 bottom
R1859  100R2F-L1-GP-U  [R402H14]  64.78 60.11 135 top
R1860  20KR2J-L2-GP  [R402H16]  71.3 25.12 90 top
R1861  100KR2J-1-GP  [R402H16]  57.43 37.24 180 bottom
R1862  20KR2J-L2-GP  [R402H16]  59.99 51.39 45 top
R1863  20KR2J-L2-GP  [R402H16]  62.14 46.2 90 top
R1864  1KR2J-1-GP  [R402H16]  59.56 25.66 270 top
R1873  100R2F-L1-GP-U  [R402H14]  68.55 67.83 135 bottom
R1874  100R2F-L1-GP-U  [R402H14]  69.76 69.04 135 bottom
R1875  100R2F-L1-GP-U  [R402H14]  83.32 68.61 0 bottom
R1901  -  [0R0402-PAD]  73.23 45.29 225 top
R1902  10KR2J-3-GP  [R402H16]  79.76 82.68 180 bottom
R1903  -  [0R0402-PAD]  72.14 46.04 135 top
R1904  10KR2J-3-GP  [R402H16]  74.41 79.39 270 bottom
R1905  0R2J-2-GP  [R402H16]  74.68 80.65 0 bottom
R1906  -  [0R0402-PAD]  70.8 46.53 135 top
R1907  -  [0R0402-PAD]  71.99 47.72 315 top
R1909  33R2J-2-GP  [R402H16]  67.26 60.14 225 top
R1910  10R2J-2-GP  [R402H14]  64.78 65.11 135 top
R1911  10R2J-2-GP  [R402H14]  66.73 64.89 135 top
R1926  75R2F-2-GP  [R402H16]  70.43 63.3 0 top
R1927  75R2F-2-GP  [R402H16]  67.79 60.76 45 top
R1928  75R2F-2-GP  [R402H16]  71.27 63.11 0 top
R1929  75R2F-2-GP  [R402H16]  72.95 63.11 0 top
R1930  402R2F-GP  [R402H16]  68.77 47.06 315 top
R1931  402R2F-GP  [R402H16]  74.06 46.3 135 top
R2400  10KR2J-3-GP  [R402H16]  51.41 21.38 270 bottom
R2401  33R2J-2-GP  [R402H16]  61.96 18.02 180 top
R2403  10KR2J-3-GP  [R402H16]  55.53 28.53 90 top
R2404  0R2J-2-GP  [R402H16]  51.34 4.04 0 bottom
R2405  10KR2J-3-GP  [R402H16]  51.85 2.84 270 top
R2407  10KR2J-3-GP  [R402H16]  69.78 23.06 270 top
R2408  2D2R3-1-U-GP  [R603H22]  51.9 19.78 0 bottom
R2409  -  [0R0603-PAD]  51.21 13.01 90 bottom
R2410  100KR2J-1-GP  [R402H16]  55.17 6.89 0 bottom
R2411  0R2J-2-GP  [R402H16]  66.75 28.35 180 bottom
R2413  -  [0R0402-PAD]  60.39 21.84 270 top
R2414  -  [0R0402-PAD]  54.36 6.89 0 bottom
R2415  -  [0R0402-PAD]  51.98 13.43 0 top
R2416  33R2J-2-GP  [R402H16]  63.02 21.31 180 top
R2417  -  [0R0402-PAD]  57.37 10.85 270 top
R2418  33R2J-2-GP  [R402H16]  62.19 21.14 180 top
R2419  1KR2J-1-GP  [R402H16]  53.35 31.5 270 bottom
R2420  10KR2J-3-GP  [R402H16]  50.49 30.67 180 bottom
R2421  10KR2J-3-GP  [R402H16]  51.62 30.81 180 bottom
R2424  -  [0R0402-PAD]  65.23 25.16 180 top
R2425  -  [0R0402-PAD]  51.33 17.93 90 bottom
R2426  10KR2J-3-GP  [R402H16]  60.66 6.2 180 top
R2427  10KR2J-3-GP  [R402H16]  66.05 25.16 0 top
R2428  10KR2J-3-GP  [R402H16]  71.8 23.92 270 top
R2430  10KR2F-2-GP  [R402H16]  57.81 28.36 180 bottom
R2434  100KR2J-1-GP  [R402H16]  52.79 15.63 180 top
R2435  -  [0R0402-PAD]  50.88 24.56 270 bottom
R2436  10KR2J-3-GP  [R402H16]  51.08 25.42 90 bottom
R2437  47KR2J-2-GP  [R402H16]  51.2 10.51 180 bottom
R2438  100KR2F-L1-GP  [R402H16]  52.91 11.57 0 bottom
R2439  -  [0R0402-PAD]  61.14 25.88 0 top
R2440  -  [0R0402-PAD]  64.41 25.16 180 top
R2442  100KR2J-1-GP  [R402H16]  67.64 28.29 0 bottom
R2443  -  [0R0402-PAD]  59.05 27.73 180 bottom
R2445  8K2R2J-3-GP  [R402H16]  59.84 21.02 270 top
R2461  -  [0R0402-PAD]  59.85 20.2 90 top
R2462  10KR2J-3-GP  [R402H16]  73.35 10.12 180 bottom
R2464  10KR2J-3-GP  [R402H16]  61.21 7.05 0 bottom
R2468  1KR2J-1-GP  [R402H16]  72.53 10.13 180 bottom
R2471  10KR2J-3-GP  [R402H16]  51.51 14.42 0 bottom
R2475  10KR2J-3-GP  [R402H16]  56.99 28.36 180 bottom
R2486  -  [0R0402-PAD]  58.94 9.45 180 top
R2487  -  [0R0402-PAD]  63.79 2.87 180 top
R2488  -  [0R0402-PAD]  55.98 6.89 0 bottom
R2489  330KR2J-L1-GP  [R402H16]  56.79 6.89 180 bottom
R2490  10KR2J-3-GP  [R402H16]  61.9 4.19 90 top
R2491  330KR2J-L1-GP  [R402H16]  62.26 2.47 270 top
R2492  20KR2J-L2-GP  [R402H16]  62.26 3.28 270 top
R2493  1KR2J-1-GP  [R402H16]  63.4 5.01 0 top
R2494  0R2J-2-GP  [R402H16]  53.98 14.38 90 top
R2495  -  [0R0402-PAD]  52.59 16.97 270 top
R2496  -  [0R0402-PAD]  62.33 25.18 180 top
R2501  1KR2J-1-GP  [R402H16]  137.23 100.12 180 bottom
R2505  10MR2J-L-GP  [R402H16]  132.13 100.55 270 top
R2511  -  [0R0402-PAD]  144.7 60.39 180 top
R2512  -  [0R0402-PAD]  138.61 71.79 90 top
R2513  0R2J-2-GP  [R402H16]  130.85 96.34 90 bottom
R2514  0R2J-2-GP  [R402H16]  135.45 100.55 270 top
R2516  0R2J-2-GP  [R402H16]  135.03 80.57 0 bottom
R2517  33R2J-2-GP  [R402H16]  142.33 60.2 180 top
R2521  -  [0R0402-PAD]  136 61.92 270 bottom
R2522  -  [0R0402-PAD]  136 61.09 270 bottom
R2523  -  [0R0402-PAD]  142.72 63.13 90 bottom
R2524  -  [0R0402-PAD]  142.72 62.32 90 bottom
R2525  -  [0R0402-PAD]  142.72 61.5 90 bottom
R2526  -  [0R0402-PAD]  142.34 60.12 0 bottom
R2527  0R2J-2-GP  [R402H16]  138.72 66.44 0 bottom
R2528  -  [0R0402-PAD]  134.67 65.09 0 bottom
R2529  10R2J-2-GP  [R402H14]  139.69 78.03 90 top
R2530  -  [0R0402-PAD]  135.98 60.21 270 bottom
R2531  10R2J-2-GP  [R402H14]  142.71 78.75 180 top
R2532  -  [0R0402-PAD]  136.41 63.48 0 bottom
R2536  10R2J-2-GP  [R402H14]  137.89 66.45 0 bottom
R2601  -  [0R0402-PAD]  71.61 74.34 0 bottom
R2602  0R2J-2-GP  [R402H16]  55.63 2.93 0 top
R2603  -  [0R0402-PAD]  53.57 2.47 90 top
R2604  NTC-100K-8-GP  [NTC-603H38]  85.28 29.16 0 bottom
R2605  18K7R2F-GP  [R402H16]  97.03 66.75 0 bottom
R2606  2KR2F-3-GP  [R402H16]  91.14 65.43 180 bottom
R2607  0R2J-2-GP  [R402H16]  74.14 76.23 0 bottom
R2608  24K9R2F-L-GP  [R402H16]  51.62 7.07 270 bottom
R2609  -  [0R0402-PAD]  72.89 74.75 90 bottom
R2612  NTC-100K-8-GP  [NTC-603H38]  49.65 10.85 0 top
R2613  -  [0R0402-PAD]  52.98 8.79 180 bottom
R2614  24K9R2F-L-GP  [R402H16]  52.26 6.22 270 bottom
R2615  2KR2J-1-GP  [R402H16]  56.46 2.93 0 top
R2701  -  [0R0402-PAD]  145.05 95.95 180 top
R2702  100KR2J-1-GP  [R402H16]  145.27 93.69 180 bottom
R2703  -  [0R0603-PAD]  146.2 82.65 0 top
R2704  100KR2J-1-GP  [R402H16]  142.32 85.73 0 top
R2705  -  [0R0402-PAD]  134.65 88.48 0 top
R2706  -  [0R0603-PAD]  148.41 84.26 90 top
R2707  20KR2F-L-GP  [R402H16]  145.87 91.65 180 bottom
R2708  -  [0R0402-PAD]  134.26 93.88 270 bottom
R2709  200KR2J-L1-GP  [R402H16]  146.31 93.69 0 bottom
R2711  -  [0R0402-PAD]  144.04 92.84 180 top
R2712  10KR2J-3-GP  [R402H16]  133.01 94.43 0 bottom
R2713  -  [0R0402-PAD]  135.74 85.6 0 top
R2714  -  [0R0402-PAD]  136.78 95.83 180 bottom
R2716  -  [0R0402-PAD]  137.62 95.84 180 bottom
R2717  1KR2J-1-GP  [R402H16]  126.47 96.85 270 top
R2718  75R2F-2-GP  [R402H16]  139.59 97.19 90 top
R2719  1KR2J-1-GP  [R402H16]  132.17 94.43 180 bottom
R2901  PBY160808T-121Y-GP  [L1608-UH38]  93.91 99.64 90 bottom
R2902  PBY160808T-121Y-GP  [L1608-UH38]  93.91 98.34 90 bottom
R2903  PBY160808T-121Y-GP  [L1608-UH38]  93.88 96.04 90 bottom
R2904  PBY160808T-121Y-GP  [L1608-UH38]  93.88 94.76 90 bottom
R2905  100KR2J-1-GP  [R402H16]  146.49 93.66 0 top
R2906  -  [0R0603-PAD]  150.85 96.55 90 top
R2907  -  [0R0603-PAD]  150.43 89.23 180 top
R2908  10R2F-L-GP  [R402H14]  139.76 84.31 0 top
R2909  -  [0R0603-PAD]  149.25 89.23 180 top
R2910  10R2F-L-GP  [R402H14]  138.93 84.31 0 top
R2911  -  [0R0603-PAD]  150.67 95.25 90 top
R2912  4K7R2J-2-GP  [R402H16]  140.59 84.31 0 top
R2913  4K7R2J-2-GP  [R402H16]  142.33 84.03 0 top
R2914  0R3J-6-GP  [R603H22]  147.59 94.56 0 top
R2915  470KR2J-2-GP  [R402H16]  151.74 87.36 0 bottom
R2918  100KR2J-1-GP  [R402H16]  146.04 96.25 0 bottom
R2919  10KR2J-3-GP  [R402H16]  140.56 82.68 180 bottom
R2920  10KR2J-3-GP  [R402H16]  141.41 82.68 180 bottom
R2921  1KR2J-1-GP  [R402H16]  149.24 86.84 90 top
R2922  1KR2J-1-GP  [R402H16]  149.23 86.01 90 top
R2923  0R3J-6-GP  [R603H22]  144.99 95.9 180 bottom
R3302  -  [0R0402-PAD]  8.71 37.06 270 bottom
R3303  -  [0R0402-PAD]  15.9 42.88 0 top
R3304  6K2R2F-GP  [R402H16]  13.63 38.37 90 top
R3307  10KR2J-3-GP  [R402H16]  9.65 40.29 270 bottom
R3308  100KR2J-1-GP  [R402H16]  10.03 42.83 270 top
R3309  -  [0R0402-PAD]  7.43 42.89 180 top
R3311  -  [0R0402-PAD]  9.73 41.56 0 bottom
R3502  -  [0R0402-PAD]  25.37 41.76 90 bottom
R3503  -  [0R0402-PAD]  25.37 42.57 90 bottom
R3509  -  [0R0402-PAD]  25.27 44.6 90 bottom
R3512  -  [0R0402-PAD]  25.27 45.42 90 bottom
R3605  100KR2J-1-GP  [R402H16]  20.6 59.62 0 bottom
R4001  -  [0R0402-PAD]  149.53 35.28 0 top
R4002  4K7R2J-2-GP  [R402H16]  48.37 13.87 90 bottom
R4003  -  [0R0402-PAD]  144.07 44.78 180 top
R4004  0R2J-2-GP  [R402H16]  49.61 14.6 0 bottom
R4005  200KR2J-L1-GP  [R402H16]  150.44 39.91 0 bottom
R4008  100KR2J-1-GP  [R402H16]  138.94 50.73 180 bottom
R4010  -  [0R0402-PAD]  150.35 35.25 0 top
R4011  100KR2J-1-GP  [R402H16]  149.91 28.92 270 bottom
R4014  100KR2J-1-GP  [R402H16]  145.16 40.21 270 bottom
R4015  -  [0R0402-PAD]  137.83 49.02 270 bottom
R4016  0R2J-2-GP  [R402H16]  148.51 33.55 90 bottom
R4017  -  [0R0402-PAD]  143.75 33.45 90 top
R4019  -  [0R0402-PAD]  135.34 48.16 90 bottom
R4020  10KR2J-3-GP  [R402H16]  137.58 54.32 90 bottom
R4021  0R2J-2-GP  [R402H16]  48.25 10.05 270 bottom
R4022  0R2J-2-GP  [R402H16]  47.88 10.18 270 top
R4024  10KR2J-3-GP  [R402H16]  136.12 49.84 270 bottom
R4027  220R3F-1-GP  [R603H22]  145.36 37.62 0 bottom
R4029  -  [0R0402-PAD]  139.83 50.73 180 bottom
R4031  10KR2J-3-GP  [R402H16]  136.12 49.01 270 bottom
R4047  1KR2J-1-GP  [R402H16]  143.21 44.3 180 bottom
R4048  1KR2J-1-GP  [R402H16]  140.61 39.38 270 bottom
R4053  100KR2J-1-GP  [R402H16]  142.36 44.3 180 bottom
R4055  -  [0R0402-PAD]  140.93 38.99 0 top
R4064  -  [0R0402-PAD]  39.99 15.85 90 top
R4065  0R2J-2-GP  [R402H16]  41.99 13.1 180 bottom
R4301  -  [0R0402-PAD]  112.15 16.83 180 top
R5401  -  [0R0603-PAD]  51.77 39.27 270 bottom
R5501  -  [0R0402-PAD]  57.85 83.76 90 top
R5502  -  [0R0402-PAD]  55.04 82.58 90 bottom
R5503  -  [0R0402-PAD]  64.78 77.99 0 bottom
R5505  100KR2J-1-GP  [R402H16]  49.82 81.22 270 top
R5506  100KR2J-1-GP  [R402H16]  58.34 87.68 270 top
R5507  100KR2J-1-GP  [R402H16]  58.33 81.97 180 top
R5508  100KR2J-1-GP  [R402H16]  65.61 77.99 0 bottom
R5516  2K2R2J-2-GP  [R402H16]  61.07 81.08 180 bottom
R5517  10KR2J-3-GP  [R402H16]  47.61 81.28 180 top
R5518  -  [0R0402-PAD]  59.15 81.97 0 top
R5521  2K2R2J-2-GP  [R402H16]  56.42 79.81 0 bottom
R5522  100KR2J-1-GP  [R402H16]  59.8 81.5 90 bottom
R5524  0R2J-2-GP  [R402H16]  49.82 80.4 90 top
R5526  2K2R2J-2-GP  [R402H16]  56.44 78.86 0 top
R5527  2K2R2J-2-GP  [R402H16]  51.56 80.06 270 top
R5702  -  [0R0402-PAD]  16.38 83.39 90 top
R5703  100KR2J-1-GP  [R402H16]  16.38 82.5 270 top
R5705  10KR2J-3-GP  [R402H16]  9.74 65.68 0 bottom
R5714  150R2F-1-GP  [R402H16]  17.01 77.55 0 top
R5715  150R2F-1-GP  [R402H16]  16.86 69.43 0 top
R5716  150R2F-1-GP  [R402H16]  16.86 67.65 0 top
R5717  150R2F-1-GP  [R402H16]  17.06 79.33 0 top
R6101  -  [0R0402-PAD]  166.21 84.88 270 top
R6102  -  [0R0402-PAD]  146.42 77.86 90 bottom
R6103  -  [0R0402-PAD]  146.42 77.02 90 bottom
R6104  -  [0R0402-PAD]  166.21 84.01 270 top
R6105  -  [0R0603-PAD]  172.35 93.54 90 top
R6106  0R2J-2-GP  [R402H16]  170.06 80.02 90 top
R6107  0R2J-2-GP  [R402H16]  175.63 84.73 270 top
R6108  0R2J-2-GP  [R402H16]  175.48 85.54 270 top
R6309  10R2J-2-GP  [R402H14]  106.29 89.24 180 top
R6310  0R3J-0-U-GP  [R603H22]  111.46 92.56 180 top
R6311  0R3J-0-U-GP  [R603H22]  95.52 91.03 270 bottom
R6312  10R2J-2-GP  [R402H14]  109.05 91.67 270 top
R6313  10R2J-2-GP  [R402H14]  104.15 89.68 270 top
R6314  10R2J-2-GP  [R402H14]  107.95 89.24 180 top
R6315  10R2J-2-GP  [R402H14]  115.7 91.01 270 bottom
R6316  10R2J-2-GP  [R402H14]  115.7 93.04 270 bottom
R6317  10R2J-2-GP  [R402H14]  115.7 95.07 270 bottom
R6318  10R2J-2-GP  [R402H14]  115.7 88.98 270 bottom
R6319  10R2J-2-GP  [R402H14]  115.7 89.99 270 bottom
R6320  10R2J-2-GP  [R402H14]  115.7 92.03 270 bottom
R6321  10R2J-2-GP  [R402H14]  115.7 94.06 270 bottom
R6322  10R2J-2-GP  [R402H14]  115.73 95.9 270 bottom
R6324  -  [0R0603-PAD]  112.75 92.56 0 top
R6325  -  [0R0603-PAD]  95.4 92.33 90 bottom
R6326  10KR2J-3-GP  [R402H16]  124.79 98.84 270 top
R6327  -  [0R0402-PAD]  126.5 98.83 90 top
R6328  -  [0R0402-PAD]  128.18 98.83 90 top
R6329  10KR2J-3-GP  [R402H16]  105.45 89.25 0 top
R6330  10KR2J-3-GP  [R402H16]  117.47 91.01 270 bottom
R6331  10KR2J-3-GP  [R402H16]  117.47 93.04 270 bottom
R6332  10KR2J-3-GP  [R402H16]  117.47 95.07 270 bottom
R6333  10KR2J-3-GP  [R402H16]  117.47 88.98 270 bottom
R6334  10KR2J-3-GP  [R402H16]  117.47 89.99 270 bottom
R6335  10KR2J-3-GP  [R402H16]  117.47 92.03 270 bottom
R6336  10KR2J-3-GP  [R402H16]  117.47 94.06 270 bottom
R6337  10KR2J-3-GP  [R402H16]  117.47 96.09 270 bottom
R6338  10KR2J-3-GP  [R402H16]  107.13 89.24 0 top
R6406  0R2J-2-GP  [R402H16]  7.41 15.96 180 top
R6407  499R2F-2-GP  [R402H16]  8.09 12.72 270 top
R6408  330R2J-3-GP  [R402H16]  12.47 12.72 270 top
R6409  0R2J-2-GP  [R402H16]  9.96 13.61 270 top
R6501  -  [0R0402-PAD]  43.29 4.83 0 top
R6502  -  [0R0402-PAD]  75.85 13.16 90 top
R6503  1KR2J-1-GP  [R402H16]  75.77 16.58 0 bottom
R6504  4K7R2J-2-GP  [R402H16]  54.33 8.94 180 top
R6505  220R2J-L2-GP  [R402H16]  46.38 8.05 270 top
R6506  220R2J-L2-GP  [R402H16]  49.13 4.34 270 top
R6508  -  [0R0402-PAD]  39.21 5.04 270 top
R6509  -  [0R0402-PAD]  39.21 5.87 270 top
R6510  0R2J-2-GP  [R402H16]  45.43 6.92 0 bottom
R6511  2K2R2J-2-GP  [R402H16]  44.15 7.34 270 bottom
R6512  2K2R2J-2-GP  [R402H16]  37.03 8.86 270 top
R6513  0R2J-2-GP  [R402H16]  42.01 2.96 0 bottom
R6514  0R2J-2-GP  [R402H16]  47.67 2.94 180 top
R6515  -  [0R0402-PAD]  100.84 14.4 90 top
R6516  1KR2J-1-GP  [R402H16]  46.3 2.52 270 top
R6518  0R2J-2-GP  [R402H16]  48.49 2.93 180 top
R6701  100KR2J-1-GP  [R402H16]  7.95 36.67 90 top
R6901  0R2J-2-GP  [R402H16]  54.1 92.58 90 top
R6902  10KR2J-3-GP  [R402H16]  58.6 92.1 180 top
R6903  0R2J-2-GP  [R402H16]  58.17 93.45 90 top
R6905  10KR2J-3-GP  [R402H16]  59.87 90.78 270 top
R6906  0R2J-2-GP  [R402H16]  63.8 87.63 180 top
R6907  0R2J-2-GP  [R402H16]  64.64 87.63 180 top
RAM1  MT41K256M16HA-125-E-GP  [BGA96D0914H48]  123 49.9 270 bottom
RAM2  MT41K256M16HA-125-E-GP  [BGA96D0914H48]  123 67.8 270 bottom
RAM3  MT41K256M16HA-125-E-GP  [BGA96D0914H48]  123 36.7 270 bottom
RAM4  MT41K256M16HA-125-E-GP  [BGA96D0914H48]  123 81 270 bottom
RN801  SRN10KJ-5-GP  [ARES2H18]  54.15 55.86 270 bottom
RN803  SRN2K2J-1-GP  [ARES2H16]  85.95 41.79 315 top
RN1501  SRN100KJ-6-GP  [SMD-ARES4]  81.92 43.05 135 top
RN1502  SRN4K7J-8-GP  [SMD-ARES4H18]  92.86 35.41 315 bottom
RN1601  SRN2K2J-1-GP  [ARES2H16]  74.47 78.3 180 top
RN1603  SRN2K2J-1-GP  [ARES2H16]  62.45 66.58 225 bottom
RN1607  SRN10KJ-5-GP  [ARES2H18]  55.75 55.73 270 top
RN1801  SRN10KJ-5-GP  [ARES2H18]  55.69 53.72 90 top
RN1802  SRN0J-7-GP-U  [ARES8-CN24H22]  62.03 60.63 180 top
RN1803  SRN10KJ-5-GP  [ARES2H18]  59.74 43.61 270 bottom
RN1805  SRN51J-1-GP  [ARES8-CN24H22]  94.66 34.32 45 bottom
RN1806  SRN51J-GP  [SMD-ARES4H18]  92.32 31.77 225 bottom
RN1901  SRN10KJ-5-GP  [ARES2H18]  76.59 64.98 135 top
RN1902  SRN10KJ-5-GP  [ARES2H18]  76.49 78.31 180 top
RN2401  SRN2K2J-1-GP  [ARES2H16]  69.61 12.37 90 top
RN2402  SRN10KJ-5-GP  [ARES2H18]  57.79 4.92 270 top
RN2403  SRN100KJ-6-GP  [SMD-ARES4]  66.34 12.04 270 top
RN2501  SRN4K7J-10-GP  [ARES8-CN24H20]  139.24 73.25 180 top
RN2601  SRN2K2J-1-GP  [ARES2H16]  96.44 78.13 0 bottom
RN2701  SRN0J-6-GP  [SMD-ARES4H20]  126.78 89.97 180 bottom
RN2901  SRN2K2J-1-GP  [ARES2H16]  146.34 90.35 90 top
RN4001  SRN10KJ-5-GP  [ARES2H18]  41.94 8.33 180 top
RN4301  SRN100J-4-GP  [ARES8-CN24H20]  108.71 18.39 270 top
RN4501  SRN0J-6-GP  [SMD-ARES4H20]  45.91 17.64 90 top
RN5501  SRN100J-4-GP  [ARES8-CN24H20]  55.77 87.62 90 top
RN5502  SRN33J-5-GP-U  [SMD-ARES4H18]  55.99 83.53 180 top
RN5701  SRN2K2J-1-GP  [ARES2H16]  16.08 76.24 90 bottom
RN5702  SRN470J-3-GP  [ARES8-CN24H20]  14.91 68.62 90 top
RN5703  SRN470J-3-GP  [ARES8-CN24H20]  14.99 78.51 90 top
RN5704  SRN10KJ-5-GP  [ARES2H18]  19.46 62.54 180 top
RN6502  SRN33J-5-GP-U  [SMD-ARES4H18]  38.84 12.98 0 top
RN6503  SRN10KJ-5-GP  [ARES2H18]  38.89 8.85 0 top
RN6901  SRN2K2J-1-GP  [ARES2H16]  60.02 92.76 180 top
RTC1  ACES-CON2-20-GP-U  [50224-0020N-W02]  142.8 100 270 bottom
SD1  SKT-SDCARD-49-GP-U  [PTFBT4-09GLBS1NN4H2]  2.75 26 90 bottom
SPK1  ACES-CON4-29-GP  [50224-0040N-001]  82 98.1 90 bottom
SPR1  SPRING-171-GP  [SPR5128H111]  139.2 43.3 270 bottom
SPR2  SPRING-171-GP  [SPR5128H111]  103 82 90 bottom
SPR3  SPRING-171-GP  [SPR5128H111]  99.42 46.38 90 bottom
SPR4  SPRING-98-GP  [SPR5432H83]  113.56 34.3 0 top
SPR5  SPRING-98-GP  [SPR5432H83]  109.55 79.45 0 top
SPR6  SPRING-98-GP  [SPR5432H83]  111.27 66.88 270 top
SSKT1  SKT-G6179HT0321-001-GP  [G6179HT0321-001]  138.21 73.83 180 bottom
TP501  TPAD14-OP-GP  [TPAD14-OP]  81.28 55.76 0 top
TP502  TPAD14-OP-GP  [TPAD14-OP]  82.68 56.75 0 top
TP801  TPAD14-OP-GP  [TPAD14-OP]  82.11 41.11 0 top
TP802  TPAD14-OP-GP  [TPAD14-OP]  83.48 39.84 0 top
TP805  TPAD14-OP-GP  [TPAD14-OP]  63.04 54.74 0 top
TP806  TPAD14-OP-GP  [TPAD14-OP]  59.5 56.59 0 top
TP807  TPAD14-OP-GP  [TPAD14-OP]  80.81 47.21 0 top
TP808  TPAD14-OP-GP  [TPAD14-OP]  82.86 45.13 0 top
TP809  TPAD14-OP-GP  [TPAD14-OP]  81.91 46.11 0 top
TP810  TPAD14-OP-GP  [TPAD14-OP]  86.73 39.17 180 bottom
TP811  TPAD14-OP-GP  [TPAD14-OP]  83.91 44.16 0 top
TP812  TPAD14-OP-GP  [TPAD14-OP]  85.56 38.78 180 bottom
TP813  TPAD14-OP-GP  [TPAD14-OP]  84.67 37.93 180 bottom
TP814  TPAD14-OP-GP  [TPAD14-OP]  87.22 40.29 180 bottom
TP901  TPAD14-OP-GP  [TPAD14-OP]  96.9 51.46 0 top
TP902  TPAD14-OP-GP  [TPAD14-OP]  56.31 52.3 180 bottom
TP1608  TPAD14-OP-GP  [TPAD14-OP]  68.96 61.06 0 top
TP1609  TPAD14-OP-GP  [TPAD14-OP]  70.13 60.68 0 top
TP1610  TPAD14-OP-GP  [TPAD14-OP]  70.96 59.75 0 top
TP1611  TPAD14-OP-GP  [TPAD14-OP]  71.72 58.79 0 top
TP1612  TPAD14-OP-GP  [TPAD14-OP]  65.38 64.26 180 bottom
TP1613  TPAD14-OP-GP  [TPAD14-OP]  91.08 39.02 180 bottom
TP1614  TPAD14-OP-GP  [TPAD14-OP]  94.61 36.7 180 bottom
TP1615  TPAD14-OP-GP  [TPAD14-OP]  84.85 50.09 0 top
TP1616  TPAD14-OP-GP  [TPAD14-OP]  85.76 49.27 0 top
TP1617  TPAD14-OP-GP  [TPAD14-OP]  85.41 48.03 0 top
TP1618  TPAD14-OP-GP  [TPAD14-OP]  86.29 47.17 0 top
TP1619  TPAD14-OP-GP  [TPAD14-OP]  86.74 48.51 0 top
TP1620  TPAD14-OP-GP  [TPAD14-OP]  96.73 35.12 180 bottom
TP1621  TPAD14-OP-GP  [TPAD14-OP]  96.85 36.35 180 bottom
TP1622  TPAD14-OP-GP  [TPAD14-OP]  72.2 61.17 0 top
TP1801  TPAD14-OP-GP  [TPAD14-OP]  58.39 49.17 180 bottom
TP1802  TPAD14-OP-GP  [TPAD14-OP]  63.63 47.92 0 top
TP1803  TPAD14-OP-GP  [TPAD14-OP]  66.17 53.02 0 top
TP2101  TPAD14-OP-GP  [TPAD14-OP]  55.19 54.16 90 bottom
TP2403  TPAD14-OP-GP  [TPAD14-OP]  62.79 6.55 180 bottom
TP2407  TPAD14-OP-GP  [TPAD14-OP]  60.99 27.63 180 bottom
TP2408  TPAD14-OP-GP  [TPAD14-OP]  64.7 13.67 0 top
TP2409  TPAD14-OP-GP  [TPAD14-OP]  61.34 7.6 0 top
TP2702  TPAD14-OP-GP  [TPAD14-OP]  135.65 94.71 180 bottom
TP5401  TPAD14-OP-GP  [TPAD14-OP]  14.84 82.72 270 top
TP5501  TPAD14-OP-GP  [TPAD14-OP]  59.25 82.54 180 bottom
TP6101  TPAD14-OP-GP  [TPAD14-OP]  175.24 81.86 0 top
TP6102  TPAD14-OP-GP  [TPAD14-OP]  175.45 83.07 0 top
TP6301  TPAD14-OP-GP  [TPAD14-OP]  108.76 95.56 180 top
TP6302  TPAD14-OP-GP  [TPAD14-OP]  107.66 95 180 top
TP6303  TPAD14-OP-GP  [TPAD14-OP]  105.78 95.24 180 top
TP6304  TPAD14-OP-GP  [TPAD14-OP]  103.66 94.85 180 top
TPAD1  ACES-CON8-66-GP  [51574-0084N-W01]  35 11 180 bottom
TR3301  COIL-90OHM-100MHZ-5-GP  [L125100-4P-4H24]  15.76 36.53 0 bottom
TR3503  FILTER-4P-137-GP-U  [L125100-4P-4H28]  25.06 47.35 180 bottom
TR5501  FILTER-4P-137-GP-U  [L125100-4P-4H28]  53.9 83.46 270 top
TR6601  FILTER-4P-137-GP-U  [L125100-4P-4H28]  150.72 82.7 180 bottom
U2401  NPCE985PB1DX-GP-U  [LQFP128H63]  62.58 17.51 180 bottom
U2404  G2129TL1U-GP  [SC70-6H44]  51.8 28.03 180 bottom
U2501  W25Q64FWSSIG-GP  [SOIC8-1H86]  138.21 73.8 0 bottom
U2503  NCT3950Y-GP  [DFN10G3-G265175H32]  139.36 61.96 90 bottom
